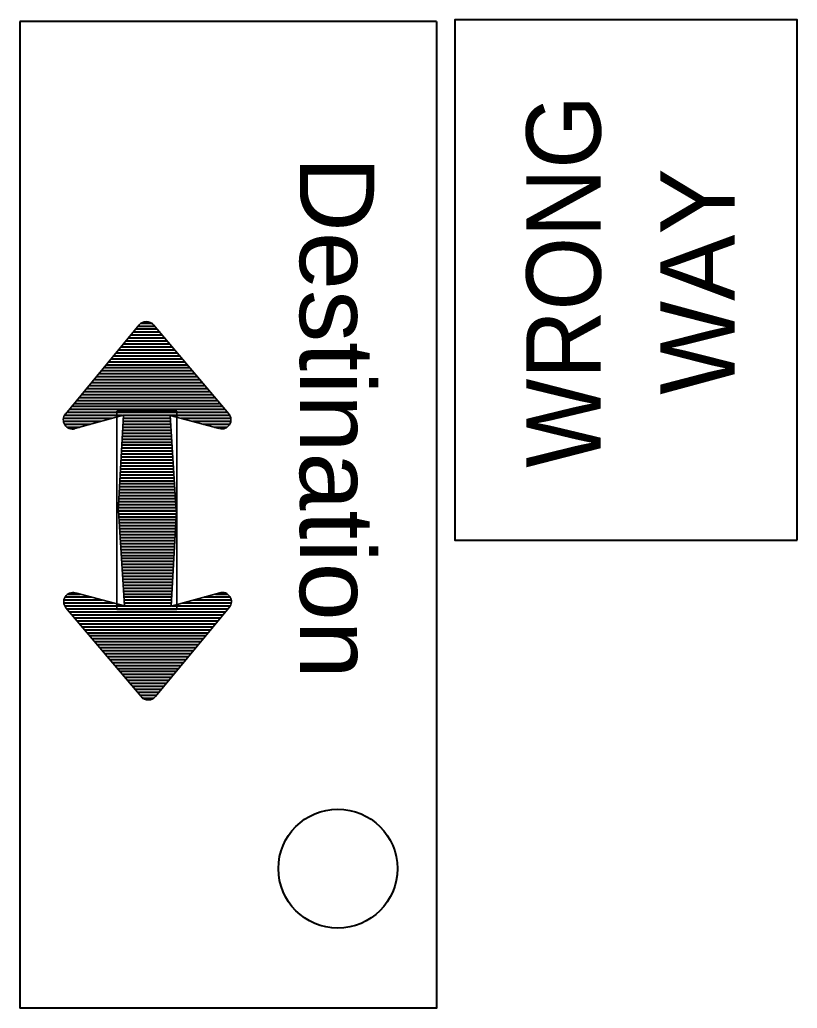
# Model space of a CAD drawing. Extents: x 1081 to 1936, y -630 to -24.
# Drawn here: x 1533.6 to 1564.94, y -292.03 to -252.15 of the extents above; entities that cross this region are included whole.
import ezdxf
from ezdxf.enums import TextEntityAlignment as Align

# ---------------------------------------------------------------- set-up
doc = ezdxf.new("R2010")
doc.units = 0
doc.layers.add('1', color=7, linetype='Continuous', lineweight=53)

msp = doc.modelspace()

# ---------------------------------------------------------------- linework, layer by layer
at = {"layer": '1', "lineweight": 40}
for p, q in [((1550.4, -252.225), (1533.601, -252.225)), ((1533.601, -252.225), (1533.601, -292.031)), ((1539.254, -264.759), (1538.174, -264.759)), ((1538.762, -264.759), (1538.174, -264.759)), ((1539.146, -264.639), (1538.27, -264.639)), ((1538.762, -264.639), (1538.27, -264.639)), ((1539.05, -264.519), (1538.366, -264.519)), ((1538.762, -264.519), (1538.366, -264.519)), ((1539.554, -265.119), (1537.874, -265.119)), ((1538.762, -265.119), (1537.874, -265.119)), ((1539.458, -264.999), (1537.97, -264.999)), ((1538.762, -264.999), (1537.97, -264.999)), ((1539.35, -264.879), (1538.078, -264.879)), ((1538.762, -264.879), (1538.078, -264.879)), ((1539.95, -265.599), (1537.478, -265.599)), ((1538.762, -265.599), (1537.478, -265.599)), ((1539.842, -265.479), (1537.574, -265.479)), ((1538.762, -265.479), (1537.574, -265.479)), ((1539.746, -265.359), (1537.67, -265.359)), ((1538.762, -265.359), (1537.67, -265.359)), ((1539.65, -265.239), (1537.778, -265.239)), ((1538.762, -265.239), (1537.778, -265.239)), ((1540.25, -265.959), (1537.178, -265.959)), ((1538.762, -265.959), (1537.178, -265.959)), ((1540.154, -265.839), (1537.274, -265.839)), ((1538.762, -265.839), (1537.274, -265.839)), ((1540.046, -265.719), (1537.382, -265.719)), ((1538.762, -265.719), (1537.382, -265.719)), ((1540.562, -266.319), (1536.878, -266.319)), ((1538.762, -266.319), (1536.878, -266.319)), ((1540.454, -266.199), (1536.986, -266.199)), ((1538.762, -266.199), (1536.986, -266.199)), ((1540.358, -266.079), (1537.082, -266.079)), ((1538.762, -266.079), (1537.082, -266.079)), ((1540.97, -266.799), (1536.482, -266.799)), ((1538.762, -266.799), (1536.482, -266.799)), ((1540.862, -266.679), (1536.59, -266.679)), ((1538.762, -266.679), (1536.59, -266.679)), ((1540.766, -266.559), (1536.686, -266.559)), ((1538.762, -266.559), (1536.686, -266.559)), ((1540.658, -266.439), (1536.782, -266.439)), ((1538.762, -266.439), (1536.782, -266.439)), ((1541.27, -267.159), (1536.182, -267.159)), ((1538.762, -267.159), (1536.182, -267.159)), ((1541.162, -267.039), (1536.29, -267.039)), ((1538.762, -267.039), (1536.29, -267.039)), ((1541.066, -266.919), (1536.386, -266.919)), ((1538.762, -266.919), (1536.386, -266.919)), ((1541.57, -267.519), (1535.894, -267.519)), ((1538.762, -267.519), (1535.894, -267.519)), ((1541.474, -267.399), (1535.99, -267.399)), ((1538.762, -267.399), (1535.99, -267.399)), ((1541.366, -267.279), (1536.086, -267.279)), ((1538.762, -267.279), (1536.086, -267.279)), ((1541.978, -267.999), (1535.498, -267.999)), ((1538.762, -267.999), (1535.498, -267.999)), ((1541.882, -267.879), (1535.594, -267.879)), ((1538.762, -267.879), (1535.594, -267.879)), ((1541.774, -267.759), (1535.69, -267.759)), ((1538.762, -267.759), (1535.69, -267.759)), ((1541.678, -267.639), (1535.786, -267.639)), ((1538.762, -267.639), (1535.786, -267.639)), ((1537.31, -268.239), (1535.366, -268.239)), ((1537.31, -268.239), (1535.366, -268.239)), ((1536.866, -268.359), (1535.366, -268.359)), ((1536.866, -268.359), (1535.366, -268.359)), ((1539.686, -268.359), (1537.766, -268.359)), ((1538.762, -268.359), (1537.766, -268.359)), ((1538.762, -268.119), (1537.778, -268.119)), ((1539.674, -268.239), (1537.778, -268.239)), ((1538.762, -268.239), (1537.778, -268.239)), ((1542.11, -268.239), (1540.106, -268.239)), ((1539.698, -268.599), (1537.754, -268.599)), ((1538.762, -268.599), (1537.754, -268.599)), ((1539.71, -268.719), (1537.754, -268.719)), ((1538.762, -268.719), (1537.754, -268.719)), ((1539.686, -268.479), (1537.766, -268.479)), ((1538.762, -268.479), (1537.766, -268.479)), ((1542.062, -268.479), (1541.006, -268.479)), ((1539.722, -269.079), (1537.73, -269.079)), ((1538.762, -269.079), (1537.73, -269.079)), ((1539.734, -269.199), (1537.73, -269.199)), ((1538.762, -269.199), (1537.73, -269.199)), ((1539.71, -268.839), (1537.742, -268.839)), ((1538.762, -268.839), (1537.742, -268.839)), ((1539.722, -268.959), (1537.742, -268.959)), ((1538.762, -268.959), (1537.742, -268.959)), ((1539.746, -269.559), (1537.706, -269.559)), ((1538.762, -269.559), (1537.706, -269.559)), ((1539.746, -269.319), (1537.718, -269.319)), ((1538.762, -269.319), (1537.718, -269.319)), ((1539.746, -269.439), (1537.718, -269.439)), ((1538.762, -269.439), (1537.718, -269.439)), ((1539.758, -269.799), (1537.694, -269.799)), ((1538.762, -269.799), (1537.694, -269.799)), ((1539.77, -269.919), (1537.694, -269.919)), ((1538.762, -269.919), (1537.694, -269.919)), ((1539.758, -269.679), (1537.706, -269.679)), ((1538.762, -269.679), (1537.706, -269.679)), ((1539.794, -270.399), (1537.658, -270.399)), ((1538.762, -270.399), (1537.658, -270.399)), ((1539.782, -270.159), (1537.67, -270.159)), ((1538.762, -270.159), (1537.67, -270.159)), ((1539.794, -270.279), (1537.67, -270.279)), ((1538.762, -270.279), (1537.67, -270.279)), ((1539.782, -270.039), (1537.682, -270.039)), ((1538.762, -270.039), (1537.682, -270.039)), ((1539.818, -270.639), (1537.646, -270.639)), ((1538.762, -270.639), (1537.646, -270.639)), ((1539.818, -270.759), (1537.646, -270.759)), ((1538.762, -270.759), (1537.646, -270.759)), ((1539.806, -270.519), (1537.658, -270.519)), ((1538.762, -270.519), (1537.658, -270.519)), ((1539.842, -271.119), (1537.622, -271.119)), ((1538.762, -271.119), (1537.622, -271.119)), ((1539.83, -270.879), (1537.634, -270.879)), ((1538.762, -270.879), (1537.634, -270.879)), ((1539.842, -270.999), (1537.634, -270.999)), ((1538.762, -270.999), (1537.634, -270.999)), ((1539.854, -271.359), (1537.61, -271.359)), ((1538.762, -271.359), (1537.61, -271.359)), ((1539.866, -271.479), (1537.61, -271.479)), ((1538.762, -271.479), (1537.61, -271.479)), ((1539.854, -271.239), (1537.622, -271.239)), ((1538.762, -271.239), (1537.622, -271.239)), ((1539.902, -271.959), (1537.574, -271.959)), ((1538.762, -271.959), (1537.574, -271.959)), ((1537.585, -271.958), (1539.913, -271.958)), ((1539.89, -271.839), (1537.586, -271.839)), ((1538.762, -271.839), (1537.586, -271.839)), ((1539.878, -271.599), (1537.598, -271.599)), ((1538.762, -271.599), (1537.598, -271.599)), ((1539.878, -271.719), (1537.598, -271.719)), ((1538.762, -271.719), (1537.598, -271.719)), ((1538.725, -271.958), (1539.913, -271.958)), ((1537.597, -272.078), (1539.901, -272.078)), ((1537.609, -272.198), (1539.889, -272.198)), ((1537.609, -272.318), (1539.889, -272.318)), ((1538.725, -272.078), (1539.901, -272.078)), ((1538.725, -272.198), (1539.889, -272.198)), ((1538.725, -272.318), (1539.889, -272.318)), ((1537.621, -272.438), (1539.877, -272.438)), ((1537.633, -272.558), (1539.877, -272.558)), ((1537.633, -272.678), (1539.865, -272.678)), ((1538.725, -272.438), (1539.877, -272.438)), ((1538.725, -272.558), (1539.877, -272.558)), ((1538.725, -272.678), (1539.865, -272.678)), ((1537.645, -272.798), (1539.865, -272.798)), ((1537.645, -272.918), (1539.853, -272.918)), ((1537.657, -273.038), (1539.853, -273.038)), ((1537.669, -273.158), (1539.841, -273.158)), ((1538.725, -272.798), (1539.865, -272.798)), ((1538.725, -272.918), (1539.853, -272.918)), ((1538.725, -273.038), (1539.853, -273.038)), ((1538.725, -273.158), (1539.841, -273.158)), ((1537.669, -273.278), (1539.841, -273.278)), ((1537.681, -273.398), (1539.829, -273.398)), ((1537.693, -273.518), (1539.829, -273.518)), ((1538.725, -273.278), (1539.841, -273.278)), ((1538.725, -273.398), (1539.829, -273.398)), ((1538.725, -273.518), (1539.829, -273.518)), ((1537.693, -273.638), (1539.817, -273.638)), ((1537.705, -273.758), (1539.817, -273.758)), ((1537.705, -273.878), (1539.805, -273.878)), ((1538.725, -273.638), (1539.817, -273.638)), ((1538.725, -273.758), (1539.817, -273.758)), ((1538.725, -273.878), (1539.805, -273.878)), ((1537.717, -273.998), (1539.793, -273.998)), ((1537.729, -274.118), (1539.793, -274.118)), ((1537.729, -274.238), (1539.781, -274.238)), ((1537.741, -274.358), (1539.781, -274.358)), ((1538.725, -273.998), (1539.793, -273.998)), ((1538.725, -274.118), (1539.793, -274.118)), ((1538.725, -274.238), (1539.781, -274.238)), ((1538.725, -274.358), (1539.781, -274.358)), ((1537.741, -274.478), (1539.769, -274.478)), ((1537.741, -274.598), (1539.769, -274.598)), ((1537.753, -274.718), (1539.757, -274.718)), ((1538.725, -274.478), (1539.769, -274.478)), ((1538.725, -274.598), (1539.769, -274.598)), ((1538.725, -274.718), (1539.757, -274.718)), ((1537.765, -274.838), (1539.757, -274.838)), ((1537.765, -274.958), (1539.745, -274.958)), ((1537.777, -275.078), (1539.745, -275.078)), ((1538.725, -274.838), (1539.757, -274.838)), ((1538.725, -274.958), (1539.745, -274.958)), ((1538.725, -275.078), (1539.745, -275.078)), ((1535.425, -275.438), (1536.481, -275.438)), ((1537.777, -275.198), (1539.733, -275.198)), ((1537.789, -275.318), (1539.733, -275.318)), ((1537.801, -275.438), (1539.721, -275.438)), ((1537.801, -275.558), (1539.721, -275.558)), ((1538.725, -275.198), (1539.733, -275.198)), ((1538.725, -275.318), (1539.733, -275.318)), ((1538.725, -275.438), (1539.721, -275.438)), ((1538.725, -275.558), (1539.721, -275.558)), ((1540.621, -275.558), (1542.121, -275.558)), ((1540.621, -275.558), (1542.121, -275.558)), ((1535.377, -275.678), (1537.381, -275.678)), ((1535.509, -275.918), (1541.989, -275.918)), ((1537.813, -275.678), (1539.709, -275.678)), ((1538.725, -275.678), (1539.709, -275.678)), ((1538.725, -275.798), (1539.709, -275.798)), ((1538.725, -275.918), (1541.989, -275.918)), ((1540.177, -275.678), (1542.121, -275.678)), ((1540.177, -275.678), (1542.121, -275.678)), ((1535.605, -276.038), (1541.893, -276.038)), ((1535.713, -276.158), (1541.797, -276.158)), ((1535.809, -276.278), (1541.701, -276.278)), ((1538.725, -276.038), (1541.893, -276.038)), ((1538.725, -276.158), (1541.797, -276.158)), ((1538.725, -276.278), (1541.701, -276.278)), ((1535.917, -276.398), (1541.593, -276.398)), ((1536.013, -276.518), (1541.497, -276.518)), ((1536.121, -276.638), (1541.401, -276.638)), ((1536.217, -276.758), (1541.305, -276.758)), ((1538.725, -276.398), (1541.593, -276.398)), ((1538.725, -276.518), (1541.497, -276.518)), ((1538.725, -276.638), (1541.401, -276.638)), ((1538.725, -276.758), (1541.305, -276.758)), ((1536.325, -276.878), (1541.197, -276.878)), ((1536.421, -276.998), (1541.101, -276.998)), ((1536.517, -277.118), (1541.005, -277.118)), ((1538.725, -276.878), (1541.197, -276.878)), ((1538.725, -276.998), (1541.101, -276.998)), ((1538.725, -277.118), (1541.005, -277.118)), ((1536.625, -277.238), (1540.897, -277.238)), ((1536.721, -277.358), (1540.801, -277.358)), ((1536.829, -277.478), (1540.705, -277.478)), ((1538.725, -277.238), (1540.897, -277.238)), ((1538.725, -277.358), (1540.801, -277.358)), ((1538.725, -277.478), (1540.705, -277.478)), ((1536.925, -277.598), (1540.609, -277.598)), ((1537.033, -277.718), (1540.501, -277.718)), ((1537.129, -277.838), (1540.405, -277.838)), ((1537.237, -277.958), (1540.309, -277.958)), ((1538.725, -277.598), (1540.609, -277.598)), ((1538.725, -277.718), (1540.501, -277.718)), ((1538.725, -277.838), (1540.405, -277.838)), ((1538.725, -277.958), (1540.309, -277.958)), ((1537.333, -278.078), (1540.213, -278.078)), ((1537.441, -278.198), (1540.105, -278.198)), ((1537.537, -278.318), (1540.009, -278.318)), ((1538.725, -278.078), (1540.213, -278.078)), ((1538.725, -278.198), (1540.105, -278.198)), ((1538.725, -278.318), (1540.009, -278.318)), ((1537.645, -278.438), (1539.913, -278.438)), ((1537.741, -278.558), (1539.817, -278.558)), ((1537.837, -278.678), (1539.709, -278.678)), ((1538.725, -278.438), (1539.913, -278.438)), ((1538.725, -278.558), (1539.817, -278.558)), ((1538.725, -278.678), (1539.709, -278.678)), ((1537.933, -278.798), (1539.613, -278.798)), ((1538.029, -278.918), (1539.517, -278.918)), ((1538.137, -279.038), (1539.409, -279.038)), ((1538.233, -279.158), (1539.313, -279.158)), ((1538.725, -278.798), (1539.613, -278.798)), ((1538.725, -278.918), (1539.517, -278.918)), ((1538.725, -279.038), (1539.409, -279.038)), ((1538.725, -279.158), (1539.313, -279.158)), ((1538.341, -279.278), (1539.217, -279.278)), ((1538.437, -279.398), (1539.121, -279.398)), ((1538.725, -279.278), (1539.217, -279.278)), ((1538.725, -279.398), (1539.121, -279.398))]:
    msp.add_line(p, q, dxfattribs=at)
at = {"layer": '1', "lineweight": 35}
for p, q in [((1535.438, -268.059), (1538.414, -264.459)), ((1538.99, -264.459), (1542.026, -268.047)), ((1538.497, -279.458), (1535.461, -275.87)), ((1542.049, -275.858), (1539.073, -279.458))]:
    msp.add_line(p, q, dxfattribs=at)
at = {"layer": '1', "lineweight": 40}
for points in [[(1550.4, -252.225), (1550.4, -292.031), (1533.601, -292.031)], [(1538.762, -264.399), (1538.498, -264.399), (1538.486, -264.399)], [(1538.918, -264.399), (1538.942, -264.399), (1538.918, -264.399), (1538.498, -264.399), (1538.498, -264.399)], [(1537.742, -268.119), (1535.414, -268.119), (1535.402, -268.119)], [(1537.742, -268.119), (1535.414, -268.119), (1535.402, -268.119)], [(1542.074, -268.119), (1542.062, -268.119), (1539.662, -268.119), (1537.778, -268.119)], [(1542.11, -268.359), (1542.098, -268.359), (1540.562, -268.359)], [(1536.434, -268.479), (1535.414, -268.479), (1535.402, -268.479)], [(1536.434, -268.479), (1535.414, -268.479), (1535.402, -268.479)], [(1536.002, -268.599), (1535.522, -268.599), (1535.51, -268.599)], [(1536.002, -268.599), (1535.522, -268.599), (1535.51, -268.599)], [(1541.954, -268.599), (1541.942, -268.599), (1541.45, -268.599)], [(1535.377, -275.558), (1535.389, -275.558), (1536.925, -275.558)], [(1535.533, -275.318), (1535.545, -275.318), (1536.037, -275.318)], [(1541.053, -275.438), (1542.073, -275.438), (1542.085, -275.438)], [(1541.053, -275.438), (1542.073, -275.438), (1542.085, -275.438)], [(1541.485, -275.318), (1541.965, -275.318), (1541.977, -275.318)], [(1541.485, -275.318), (1541.965, -275.318), (1541.977, -275.318)], [(1535.413, -275.798), (1535.425, -275.798), (1537.825, -275.798), (1539.709, -275.798)], [(1539.745, -275.798), (1542.073, -275.798), (1542.085, -275.798)], [(1539.745, -275.798), (1542.073, -275.798), (1542.085, -275.798)], [(1538.569, -279.518), (1538.545, -279.518), (1538.569, -279.518), (1538.989, -279.518), (1538.989, -279.518)], [(1538.725, -279.518), (1538.989, -279.518), (1539.001, -279.518)]]:
    msp.add_lwpolyline(points, dxfattribs=at)
msp.add_lwpolyline([(1564.944, -273.149), (1564.944, -252.149), (1551.144, -252.149), (1551.144, -273.149)], close=True, dxfattribs=at)
at = {"layer": '1', "lineweight": 35}
msp.add_lwpolyline([(1539.928, -275.945), (1537.516, -275.945), (1537.516, -267.947), (1539.928, -267.947)], close=True, dxfattribs=at)
for points in [[(1541.642, -268.647), (1539.662, -268.119), (1539.902, -271.959), (1537.574, -271.959), (1537.778, -268.107), (1535.822, -268.647)], [(1535.845, -275.27), (1537.825, -275.798), (1537.585, -271.958), (1539.913, -271.958), (1539.709, -275.81), (1541.665, -275.27)]]:
    msp.add_lwpolyline(points, dxfattribs=at)
at = {"layer": '1', "lineweight": 40}
msp.add_circle((1546.426, -286.399), 2.4, dxfattribs=at)
at = {"layer": '1', "lineweight": 35}
for centre, start, end in [((1538.702, -264.697), 40.2565, 140.4047), ((1535.727, -268.292), 140.43, 285.5512), ((1541.744, -268.287), 255.1137, 40.2576), ((1535.743, -275.63), 75.1137, 220.2576), ((1541.76, -275.625), 320.43, 105.5512), ((1538.785, -279.22), 220.2565, 320.4047)]:
    msp.add_arc(centre, 0.372, start, end, dxfattribs=at)

# ---------------------------------------------------------------- texts
at = {"layer": '1'}
for s, rotation, width, p in [('WRONG', 90, 0.95, (1557.023, -262.71)), ('Destination', 270, 1.05, (1544.892, -268.202))]:
    msp.add_text(s, height=3, rotation=rotation, dxfattribs=dict(at, width=width)).set_placement(p, align=Align.CENTER)
msp.add_text('WAY', height=3, rotation=90, dxfattribs=at).set_placement((1562.423, -262.71), align=Align.CENTER)

doc.saveas('drawing.dxf')
